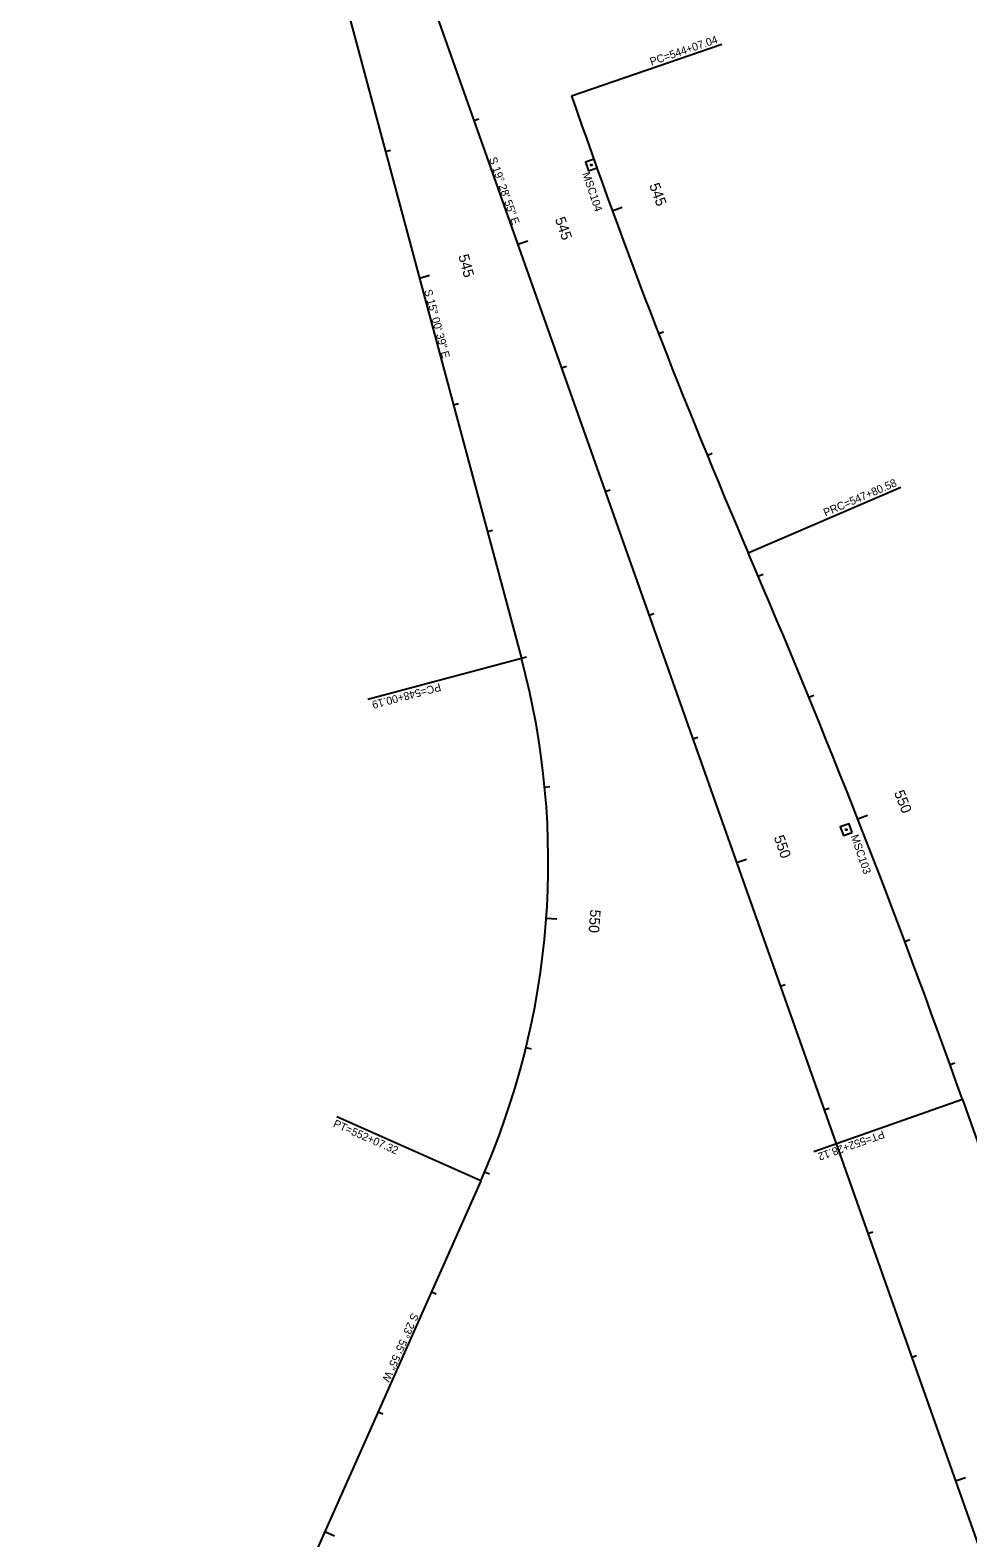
# Model space of a CAD drawing. Extents: x 2004390 to 2008791, y 1133870 to 1140084.
# Drawn here: x 2005036 to 2005751, y 1137597 to 1138747 of the extents above; entities that cross this region are included whole.
import ezdxf

# ---------------------------------------------------------------- set-up
doc = ezdxf.new("R2010")
doc.units = 0
for name, color, linetype in [('RD_HC_Cl', 7, 'Continuous'), ('RD_HC_Data', 7, 'Continuous'), ('RD_HC_Data_Tic', 7, 'Continuous'), ('RD_HC_Survey', 7, 'Continuous'), ('RD_HC_Survey_txCode', 7, 'Continuous'), ('RD_HC_TX_Sta50', 7, 'Continuous')]:
    doc.layers.add(name, color=color, linetype=linetype)

msp = doc.modelspace()

# ---------------------------------------------------------------- linework, layer by layer
at = {"layer": 'RD_HC_Cl'}
for p, q in [((2005036.1, 1139633.5), (2007075.2, 1133869.8)), ((2005274.3, 1138775.6), (2005410.4, 1138267.8)), ((2005746.4, 1137931.6), (2006120.3, 1136874.9)), ((2005379.4, 1137869.6), (2005232, 1137537.6))]:
    msp.add_line(p, q, dxfattribs=at)
for centre, radius, start, end in [((2010111.4, 1140297.9), 4930, 198.9531, 203.2944), ((1999405.5, 1135688.4), 6726, 19.48201, 23.29439), ((2004831.9, 1138112.6), 599, 336.0681, 15.0109)]:
    msp.add_arc(centre, radius, start, end, dxfattribs=at)
at = {"layer": 'RD_HC_Data'}
for p, q in [((2005448.6, 1138696.6), (2005563.1, 1138735.9)), ((2005583.2, 1138348.3), (2005699.4, 1138398.3)), ((2005410.4, 1138267.8), (2005293.5, 1138236.4)), ((2005746.4, 1137931.6), (2005633.3, 1137891.6)), ((2005379.4, 1137869.6), (2005269.7, 1137918.3))]:
    msp.add_line(p, q, dxfattribs=at)
at = {"layer": 'RD_HC_Data_Tic'}
for p, q in [((2005374.3, 1138677.8), (2005378, 1138679.1)), ((2005306.8, 1138654.3), (2005310.7, 1138655.3)), ((2005479.7, 1138609), (2005487.2, 1138611.7)), ((2005407.6, 1138583.5), (2005415.2, 1138586.2)), ((2005332.7, 1138557.7), (2005340.4, 1138559.8)), ((2005514.9, 1138515.4), (2005518.6, 1138516.8)), ((2005441, 1138489.2), (2005444.7, 1138490.6)), ((2005358.6, 1138461.1), (2005362.5, 1138462.2)), ((2005552, 1138422.5), (2005555.7, 1138424.1)), ((2005474.3, 1138394.9), (2005478.1, 1138396.3)), ((2005384.5, 1138364.5), (2005388.4, 1138365.6)), ((2005590.9, 1138330.4), (2005594.6, 1138332)), ((2005507.7, 1138300.7), (2005511.4, 1138302)), ((2005410.4, 1138268), (2005414.3, 1138269)), ((2005629.5, 1138238.2), (2005633.2, 1138239.7)), ((2005541, 1138206.4), (2005544.8, 1138207.7)), ((2005428.2, 1138169.7), (2005432.1, 1138170)), ((2005666.7, 1138145.4), (2005674.1, 1138148.3)), ((2005574.4, 1138112.1), (2005581.9, 1138114.8)), ((2005429.3, 1138069.8), (2005437.3, 1138069.2)), ((2005702.5, 1138052), (2005706.3, 1138053.4)), ((2005607.7, 1138017.9), (2005611.5, 1138019.2)), ((2005413.9, 1137971.1), (2005417.8, 1137970.2)), ((2005737, 1137958.1), (2005740.7, 1137959.5)), ((2005641.1, 1137923.6), (2005644.8, 1137924.9)), ((2005382.3, 1137876.4), (2005386, 1137874.8)), ((2005674.4, 1137829.3), (2005678.2, 1137830.6)), ((2005341.8, 1137784.9), (2005345.4, 1137783.3)), ((2005707.8, 1137735), (2005711.5, 1137736.4)), ((2005301.2, 1137693.5), (2005304.9, 1137691.9)), ((2005741.1, 1137640.8), (2005748.7, 1137643.4)), ((2005260.7, 1137602.1), (2005268, 1137598.9))]:
    msp.add_line(p, q, dxfattribs=at)
at = {"layer": 'RD_HC_Survey'}
for points in [[(2005468.2, 1138641.7), (2005465.9, 1138648.4), (2005459.2, 1138646.1), (2005461.5, 1138639.4)], [(2005662.4, 1138135.1), (2005660.1, 1138141.7), (2005653.4, 1138139.4), (2005655.8, 1138132.7)]]:
    msp.add_lwpolyline(points, close=True, dxfattribs=at)
for centre in [(2005463.7, 1138643.9), (2005657.9, 1138137.2)]:
    msp.add_circle(centre, 0.5, dxfattribs=at)

# ---------------------------------------------------------------- texts
at = {"layer": 'RD_HC_Data'}
for s, rotation, p in [('PC=544+07.04', 18.9531, (2005509.5, 1138719.6)), ('S 19%%d 28\' 55" E', 289.482, (2005385.6, 1138648.7)), ('S 15%%d 00\' 39" E', 285.0109, (2005336.3, 1138548.2)), ('PRC=547+80.58', 23.2944, (2005642.1, 1138375.8)), ('PC=548+00.19', 195.0109, (2005348.2, 1138249)), ('PT=552+07.32', 336.0681, (2005266.5, 1137911)), ('PT=552+28.12', 199.482, (2005685.8, 1137908.1)), ('S 23%%d 55\' 55" W', 246.0681, (2005327, 1137769.3))]:
    msp.add_text(s, height=6, rotation=rotation, dxfattribs=at).set_placement(p)
at = {"layer": 'RD_HC_Survey_txCode'}
for s, p in [('MSC104', (2005456.7, 1138637.3)), ('MSC103', (2005661.3, 1138132.3))]:
    msp.add_text(s, height=6, rotation=288.8025, dxfattribs=at).set_placement(p)
at = {"layer": 'RD_HC_TX_Sta50'}
for s, rotation, p in [('545', 290.0335, (2005507.7, 1138628.5)), ('545', 289.482, (2005435.8, 1138602.7)), ('545', 285.0109, (2005362.3, 1138574.7)), ('550', 291.4252, (2005694.2, 1138165.5)), ('550', 289.482, (2005602.6, 1138131.4)), ('550', 265.8984, (2005462.9, 1138076.6))]:
    msp.add_text(s, height=8, rotation=rotation, dxfattribs=at).set_placement(p)

doc.saveas('drawing.dxf')
